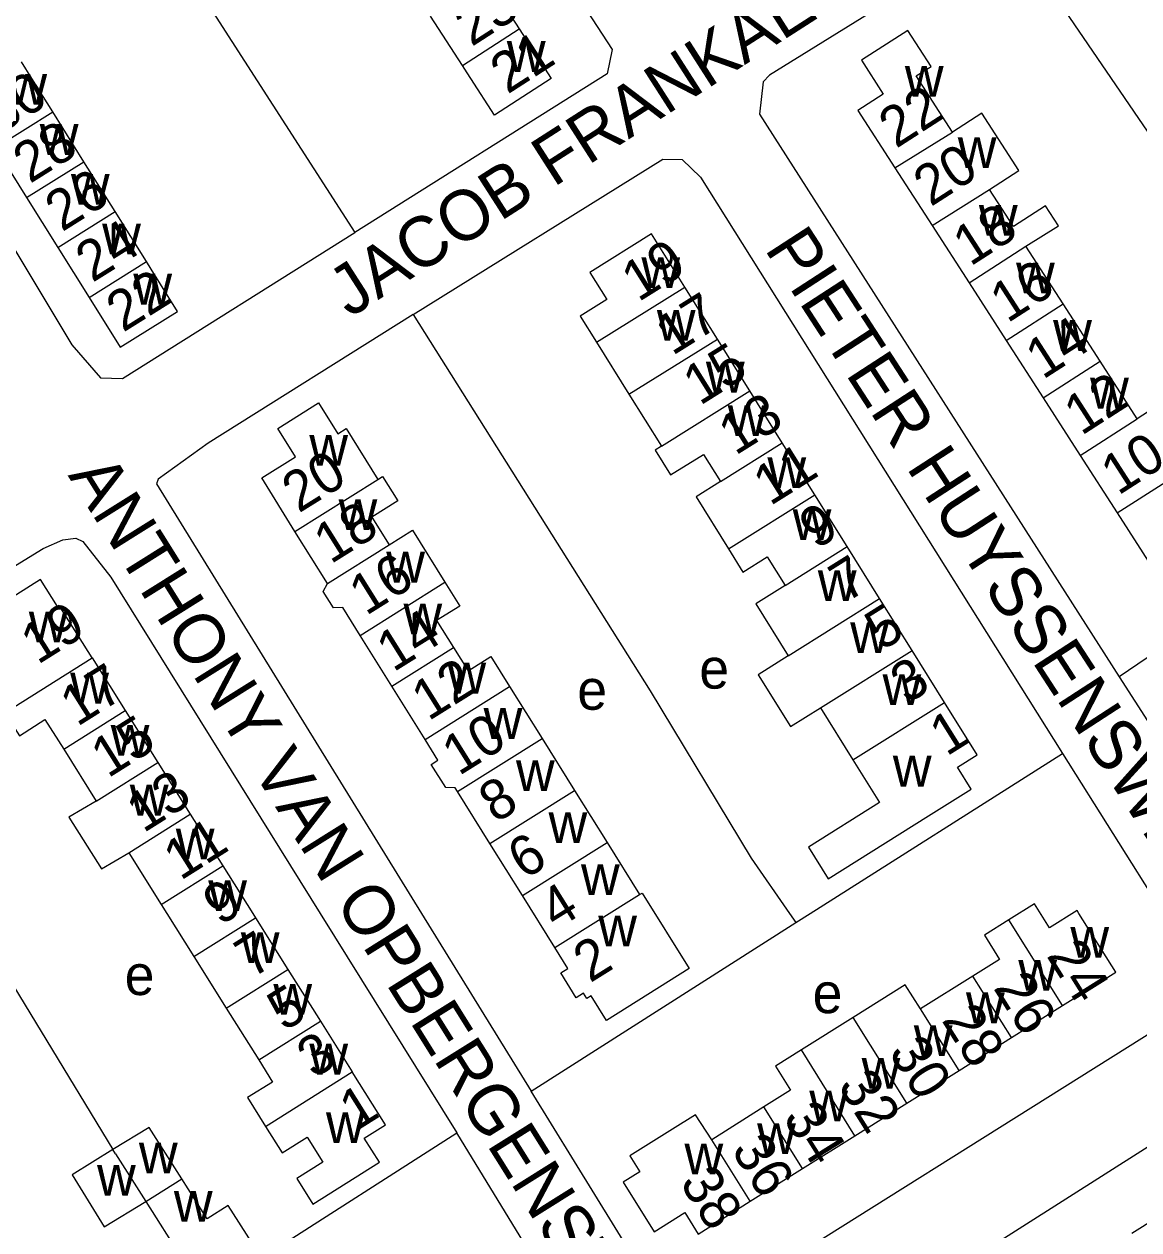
# Model space of a CAD drawing. Extents: x 158848 to 160613, y 385889 to 387762.
# Drawn here: x 159730.4 to 159841.7, y 386135.1 to 386255.4 of the extents above; entities that cross this region are included whole.
import ezdxf

# ---------------------------------------------------------------- set-up
doc = ezdxf.new("R2010")
doc.units = 0
for name, color, linetype in [('BLT_Basislijn', 7, 'Continuous'), ('BLT_Bebouwing', 7, 'Continuous'), ('BLT_Centroide', 7, 'Continuous'), ('BLT_Huisnummer', 7, 'Continuous'), ('BLT_Huisnummer_ tussenligend', 7, 'Continuous'), ('BLT_Onderverdeling_panden', 7, 'Continuous'), ('BLT_Straatnaam', 7, 'Continuous')]:
    doc.layers.add(name, color=color, linetype=linetype)

msp = doc.modelspace()

# ---------------------------------------------------------------- linework, layer by layer
at = {"layer": 'BLT_Basislijn'}
for p, q in [((159733.43, 386281.22), (159763.44, 386234.64)), ((159828.64, 386265.11), (159864.18, 386212.97)), ((159846.93, 386195.16), (159839.72, 386190.3)), ((159839.72, 386190.3), (159844.12, 386183.47)), ((159781.05, 386148.93), (159807.44, 386165.77)), ((159748.59, 386128.77), (159773.6, 386144.78))]:
    msp.add_line(p, q, dxfattribs=at)
for points in [[(159759.78, 386297.89), (159789.12, 386252.89), (159788.61, 386250.47), (159763.44, 386234.64)], [(159709.57, 386266.05), (159735.18, 386223.43), (159738.06, 386220.13), (159740.25, 386220.05), (159763.44, 386234.64)], [(159828.64, 386265.11), (159804.84, 386250.34), (159804.2, 386249.65), (159803.82, 386246.43), (159839.72, 386190.3)], [(159769.26, 386226.44), (159794.19, 386241.94), (159796.12, 386241.93), (159797.93, 386240.15), (159834.08, 386182.64)], [(159769.26, 386226.44), (159748.8, 386213.59), (159743.8, 386210.02), (159743.64, 386209.54), (159770.1, 386166.67), (159781.05, 386148.93)], [(159769.26, 386226.44), (159792.93, 386188.89), (159803.01, 386172.2), (159806.82, 386166.67), (159807.44, 386165.77)], [(159710.52, 386189.71), (159732.33, 386203.09), (159734.29, 386203.97), (159735.57, 386204.11), (159736.27, 386203.79), (159739.07, 386200.22), (159759.97, 386166.67), (159773.6, 386144.78)], [(159710.52, 386189.71), (159724.92, 386166.67), (159739.27, 386143.1)], [(159834.08, 386182.64), (159844.13, 386166.67), (159848.84, 386159.17), (159848.48, 386158.57), (159843.69, 386155.27), (159797.68, 386126.37), (159795.72, 386126.21), (159793.75, 386128.31), (159781.05, 386148.93)], [(159807.44, 386165.77), (159808.87, 386166.67), (159834.08, 386182.64)], [(159748.37, 386051.77), (159734.43, 386074.27), (159734.43, 386074.65), (159846.2, 386145.66), (159847.14, 386145.64), (159848.36, 386145.17), (159861.9, 386123.55)], [(159722.33, 386112.11), (159736.69, 386089.11), (159737.39, 386088.62), (159785.14, 386119), (159786.99, 386121.06), (159786.89, 386123.07), (159773.6, 386144.78)]]:
    msp.add_lwpolyline(points, dxfattribs=at)
at = {"layer": 'BLT_Bebouwing'}
for p, q in [((159776.67, 386259.88), (159779.85, 386254.94)), ((159774.18, 386251.28), (159771, 386256.22)), ((159736.39, 386241.69), (159733.27, 386246.67)), ((159727.56, 386243.09), (159730.67, 386238.11)), ((159739.51, 386236.71), (159736.39, 386241.69)), ((159817.35, 386241.08), (159821.05, 386235.34)), ((159730.67, 386238.11), (159733.79, 386233.13)), ((159742.62, 386231.73), (159739.51, 386236.71)), ((159821.05, 386235.34), (159824.75, 386229.6)), ((159834.13, 386227.52), (159830.43, 386233.26)), ((159733.79, 386233.13), (159736.91, 386228.15)), ((159799.62, 386224), (159796.38, 386229.19)), ((159824.75, 386229.6), (159828.45, 386223.86)), ((159837.83, 386221.78), (159834.13, 386227.52)), ((159802.86, 386218.82), (159799.62, 386224)), ((159828.45, 386223.86), (159832.14, 386218.12)), ((159841.52, 386216.04), (159837.83, 386221.78)), ((159806.1, 386213.64), (159802.86, 386218.82)), ((159832.14, 386218.12), (159835.84, 386212.38)), ((159809.34, 386208.46), (159806.1, 386213.64)), ((159835.84, 386212.38), (159839.54, 386206.64)), ((159812.58, 386203.28), (159809.34, 386208.46)), ((159839.54, 386206.64), (159843.24, 386200.9)), ((159760.71, 386199.61), (159757.46, 386204.8)), ((159815.82, 386198.09), (159812.58, 386203.28)), ((159819.06, 386192.91), (159815.82, 386198.09)), ((159767.12, 386189.35), (159763.95, 386194.42)), ((159822.3, 386187.73), (159819.06, 386192.91)), ((159737.22, 386192.18), (159740.52, 386186.92)), ((159770.44, 386184.04), (159767.12, 386189.35)), ((159778.88, 386189.32), (159782.13, 386184.13)), ((159740.52, 386186.92), (159743.77, 386181.75)), ((159809.93, 386187.2), (159813.16, 386182.01)), ((159782.13, 386184.13), (159785.37, 386178.93)), ((159734.37, 386183.05), (159737.61, 386177.88)), ((159743.77, 386181.75), (159747.01, 386176.58)), ((159776.92, 386173.65), (159773.68, 386178.85)), ((159785.37, 386178.93), (159788.61, 386173.74)), ((159747.01, 386176.58), (159750.26, 386171.41)), ((159780.17, 386168.46), (159776.92, 386173.65)), ((159788.61, 386173.74), (159791.85, 386168.55)), ((159740.86, 386172.71), (159744.1, 386167.55)), ((159753.51, 386166.25), (159756.75, 386161.08)), ((159747.35, 386162.38), (159750.6, 386157.21)), ((159756.75, 386161.08), (159760, 386155.91)), ((159825.12, 386160.42), (159819.91, 386157.15)), ((159828.97, 386154.28), (159834.09, 386157.48)), ((159750.6, 386157.21), (159753.84, 386152.05)), ((159813.19, 386156.29), (159808.01, 386153.05)), ((159760, 386155.91), (159763.17, 386150.87)), ((159823.76, 386151.01), (159828.97, 386154.28)), ((159818.55, 386147.74), (159823.76, 386151.01)), ((159804.27, 386147.36), (159799.06, 386144.09)), ((159813.33, 386144.48), (159818.55, 386147.74)), ((159808.12, 386141.22), (159813.33, 386144.48)), ((159739.53, 386142.67), (159739.27, 386143.1)), ((159802.91, 386137.95), (159808.12, 386141.22)), ((159742.57, 386137.91), (159747.48, 386130.21))]:
    msp.add_line(p, q, dxfattribs=at)
for points in [[(159779.85, 386254.94), (159783.03, 386250), (159777.36, 386246.35), (159775, 386250), (159774.65, 386250.55), (159774.18, 386251.28)], [(159823.1, 386244.64), (159819.48, 386250.25), (159820.95, 386251.19), (159818.62, 386254.8), (159814, 386251.82), (159816.18, 386248.44), (159813.65, 386246.82)], [(159733.27, 386246.67), (159731.19, 386250), (159730.16, 386251.65)], [(159813.65, 386246.82), (159817.35, 386241.08)], [(159826.78, 386238.93), (159829.71, 386240.82), (159826.02, 386246.55), (159823.1, 386244.64)], [(159830.43, 386233.26), (159833.67, 386235.29), (159832.38, 386237.29), (159829.17, 386235.22), (159826.78, 386238.93)], [(159796.38, 386229.19), (159793.06, 386234.49), (159786.89, 386230.64), (159788.59, 386227.93), (159785.92, 386226.27), (159787.55, 386223.67)], [(159736.91, 386228.15), (159740.02, 386223.17), (159745.74, 386226.74), (159743.09, 386230.98), (159742.62, 386231.73)], [(159787.55, 386223.67), (159790.8, 386218.48)], [(159757.46, 386204.8), (159754.14, 386210.13), (159757.51, 386212.23), (159755.73, 386215.07), (159759.81, 386217.62), (159761.74, 386214.54), (159762.57, 386215.06), (159765.74, 386209.98)], [(159790.8, 386218.48), (159794.05, 386213.31)], [(159845.22, 386210.3), (159848.16, 386212.19), (159844.47, 386217.93), (159841.52, 386216.04)], [(159794.05, 386213.31), (159793.41, 386212.9), (159794.95, 386210.43), (159798.23, 386212.48), (159799.92, 386209.78)], [(159765.74, 386209.98), (159766.21, 386210.28), (159767.73, 386207.85), (159765.14, 386206.23), (159766.87, 386203.47)], [(159799.92, 386209.78), (159797.49, 386208.26), (159800.73, 386203.06)], [(159766.87, 386203.47), (159769.19, 386204.92), (159772.43, 386199.73)], [(159800.73, 386203.06), (159802.18, 386200.73), (159804.61, 386202.25), (159806.39, 386199.4)], [(159737.22, 386192.18), (159733.92, 386197.42), (159733.75, 386197.32), (159732.07, 386199.99), (159724.56, 386195.27), (159726.35, 386192.43), (159725.32, 386191.78), (159728.51, 386186.7)], [(159763.95, 386194.42), (159762.22, 386197.2), (159761.31, 386197.16), (159760.27, 386198.81), (159760.71, 386199.61)], [(159772.43, 386199.73), (159773.91, 386197.35), (159771.59, 386195.9), (159773.28, 386193.2)], [(159806.39, 386199.4), (159803.46, 386197.56), (159806.69, 386192.39)], [(159773.28, 386193.2), (159774.73, 386190.88), (159777.02, 386192.31), (159778.88, 386189.32)], [(159806.69, 386192.39), (159803.68, 386190.5), (159806.92, 386185.32), (159809.93, 386187.2)], [(159813.16, 386182.01), (159815.82, 386177.74), (159808.71, 386173.29), (159810.68, 386170.14), (159820.71, 386176.41), (159824.95, 386179.06), (159823.58, 386181.26), (159825.57, 386182.5), (159822.3, 386187.73)], [(159728.51, 386186.7), (159729.95, 386184.41), (159732.5, 386186.02), (159734.37, 386183.05)], [(159773.68, 386178.85), (159773.45, 386179.21), (159772.51, 386179.23), (159771.06, 386181.55), (159771.73, 386181.97), (159770.44, 386184.04)], [(159737.61, 386177.88), (159734.89, 386176.29), (159738.13, 386171.13), (159740.86, 386172.71)], [(159750.26, 386171.41), (159753.24, 386166.67), (159753.51, 386166.25)], [(159783.41, 386163.27), (159780.17, 386168.46)], [(159791.85, 386168.55), (159792.11, 386168.71), (159796.82, 386161.17), (159788.54, 386155.99), (159787.01, 386158.45), (159786.59, 386158.18), (159786.26, 386158.7), (159785.54, 386158.25), (159783.98, 386160.74), (159784.71, 386161.19), (159783.41, 386163.27)], [(159744.1, 386167.55), (159744.66, 386166.67), (159747.35, 386162.38)], [(159834.09, 386157.48), (159839.39, 386160.8), (159835.72, 386166.67), (159835.55, 386166.95), (159832.78, 386165.22), (159831.28, 386167.63), (159828.73, 386166.03)], [(159828.73, 386166.03), (159826.28, 386164.5), (159827.79, 386162.09), (159825.12, 386160.42)], [(159819.91, 386157.15), (159818.37, 386159.54), (159813.19, 386156.29)], [(159808.01, 386153.05), (159805.43, 386151.43), (159806.93, 386149.03), (159804.27, 386147.36)], [(159753.84, 386152.05), (159755.22, 386149.85), (159752.71, 386148.29), (159754.51, 386145.42)], [(159754.51, 386145.42), (159756.17, 386142.79), (159758.67, 386144.36), (159760.24, 386141.86), (159757.65, 386140.22), (159759.25, 386137.67), (159765.89, 386141.84), (159764.38, 386144.25), (159766.49, 386145.58), (159763.17, 386150.87)], [(159799.06, 386144.09), (159797.45, 386146.58), (159795.13, 386145.13), (159790.9, 386142.48), (159791.88, 386140.9), (159790.22, 386139.86), (159793.32, 386134.91), (159796.36, 386136.82), (159797.7, 386134.68), (159802.91, 386137.95)], [(159746.17, 386140.17), (159742.9, 386145.31), (159739.27, 386143.1)], [(159739.27, 386143.1), (159735.2, 386140.6), (159738.42, 386135.39), (159742.57, 386137.91)], [(159747.48, 386130.21), (159753.15, 386133.83), (159750.8, 386137.51), (159748.7, 386136.2), (159746.17, 386140.17)], [(159844.83, 386128.58), (159850.1, 386131.89), (159846.26, 386138.03), (159840.98, 386134.72)]]:
    msp.add_lwpolyline(points, dxfattribs=at)
at = {"layer": 'BLT_Onderverdeling_panden'}
for p, q in [((159774.18, 386251.28), (159779.85, 386254.94)), ((159727.56, 386243.09), (159733.27, 386246.67)), ((159817.35, 386241.08), (159823.1, 386244.64)), ((159730.67, 386238.11), (159736.39, 386241.69)), ((159821.05, 386235.34), (159826.78, 386238.93)), ((159733.79, 386233.13), (159739.51, 386236.71)), ((159824.75, 386229.6), (159830.43, 386233.26)), ((159736.91, 386228.15), (159742.62, 386231.73)), ((159787.55, 386223.67), (159796.38, 386229.19)), ((159828.45, 386223.86), (159834.13, 386227.52)), ((159790.8, 386218.48), (159799.62, 386224)), ((159832.14, 386218.12), (159837.83, 386221.78)), ((159794.05, 386213.31), (159802.86, 386218.82)), ((159835.84, 386212.38), (159841.52, 386216.04)), ((159799.92, 386209.78), (159806.1, 386213.64)), ((159757.46, 386204.8), (159765.74, 386209.98)), ((159839.54, 386206.64), (159845.22, 386210.3)), ((159800.73, 386203.06), (159809.34, 386208.46)), ((159760.71, 386199.61), (159766.87, 386203.47)), ((159806.39, 386199.4), (159812.58, 386203.28)), ((159763.95, 386194.42), (159772.43, 386199.73)), ((159806.69, 386192.39), (159815.82, 386198.09)), ((159767.12, 386189.35), (159773.28, 386193.2)), ((159809.93, 386187.2), (159819.06, 386192.91)), ((159728.51, 386186.7), (159737.22, 386192.18)), ((159770.44, 386184.04), (159778.88, 386189.32)), ((159813.16, 386182.01), (159822.3, 386187.73)), ((159734.37, 386183.05), (159740.52, 386186.92)), ((159773.68, 386178.85), (159782.13, 386184.13)), ((159737.61, 386177.88), (159743.77, 386181.75)), ((159776.92, 386173.65), (159785.37, 386178.93)), ((159740.86, 386172.71), (159747.01, 386176.58)), ((159780.17, 386168.46), (159788.61, 386173.74)), ((159744.1, 386167.55), (159750.26, 386171.41)), ((159783.41, 386163.27), (159791.85, 386168.55)), ((159747.35, 386162.38), (159753.51, 386166.25)), ((159834.09, 386157.48), (159828.73, 386166.03)), ((159750.6, 386157.21), (159756.75, 386161.08)), ((159828.97, 386154.28), (159825.12, 386160.42)), ((159818.55, 386147.74), (159813.19, 386156.29)), ((159823.76, 386151.01), (159819.91, 386157.15)), ((159753.84, 386152.05), (159760, 386155.91)), ((159813.33, 386144.48), (159808.01, 386153.05)), ((159754.51, 386145.42), (159763.17, 386150.87)), ((159808.12, 386141.22), (159804.27, 386147.36)), ((159802.91, 386137.95), (159799.06, 386144.09)), ((159739.53, 386142.67), (159742.57, 386137.91)), ((159742.57, 386137.91), (159746.17, 386140.17))]:
    msp.add_line(p, q, dxfattribs=at)

# ---------------------------------------------------------------- texts
at = {"layer": 'BLT_Centroide'}
for s, p in [('w', (159778.61, 386250.66)), ('w', (159728.85, 386247.38)), ('w', (159818.34, 386248.17)), ('w', (159731.98, 386242.38)), ('w', (159823.62, 386241.06)), ('w', (159735.09, 386237.41)), ('w', (159825.73, 386234.3)), ('w', (159738.21, 386232.44)), ('w', (159792.04, 386229.09)), ('w', (159829.44, 386228.56)), ('w', (159741.32, 386227.44)), ('w', (159793.58, 386223.84)), ('w', (159833.14, 386222.81)), ('w', (159798.48, 386218.66)), ('w', (159836.83, 386217.06)), ('w', (159800.66, 386214.31)), ('w', (159758.89, 386211.36)), ('w', (159804.62, 386209.12)), ('w', (159761.81, 386204.94)), ('w', (159807.14, 386203.94)), ('w', (159766.57, 386199.69)), ('w', (159809.65, 386197.84)), ('w', (159768.29, 386194.53)), ('w', (159730.89, 386193.72)), ('w', (159812.88, 386192.66)), ('w', (159772.67, 386188.62)), ('e', (159797.82, 386189.11)), ('w', (159735.02, 386187.62)), ('e', (159785.64, 386187)), ('w', (159816.11, 386187.47)), ('w', (159776.29, 386184.09)), ('w', (159739.06, 386182.41)), ('w', (159779.52, 386178.88)), ('w', (159817.14, 386179.34)), ('w', (159740.97, 386176.44)), ('w', (159782.77, 386173.69)), ('w', (159745.56, 386172.06)), ('w', (159786.01, 386168.5)), ('w', (159748.8, 386166.91)), ('w', (159787.73, 386163.38)), ('w', (159752.05, 386161.72)), ('w', (159834.86, 386162.25)), ('e', (159740.46, 386158.53)), ('w', (159829.66, 386158.97)), ('e', (159809.13, 386156.72)), ('w', (159755.3, 386156.56)), ('w', (159824.44, 386155.72)), ('w', (159819.23, 386152.45)), ('w', (159758.89, 386150.59)), ('w', (159814.02, 386149.19)), ('w', (159808.8, 386145.92)), ('w', (159760.55, 386143.75)), ('w', (159803.59, 386142.66)), ('w', (159741.88, 386140.72)), ('w', (159796.34, 386140.62)), ('w', (159737.7, 386138.51)), ('w', (159745.37, 386135.9))]:
    msp.add_text(s, height=4, dxfattribs=at).set_placement(p)
at = {"layer": 'BLT_Huisnummer'}
for s, rotation, p in [('21', 32.7765, (159778.67, 386248.38)), ('30', 32.0423, (159728.01, 386244.41)), ('22', 32.7851, (159817.46, 386242.96)), ('26', 32.0423, (159734.19, 386234.64)), ('18', 32.7851, (159824.86, 386231.19)), ('19', 32.0212, (159791.73, 386227.64)), ('22', 32.0423, (159740.29, 386224.61)), ('14', 32.7851, (159832.11, 386219.9)), ('13', 32.0212, (159801.41, 386212.32)), ('10', 32.7851, (159839.63, 386208.33)), ('20', 31.9896, (159757.83, 386206.57)), ('9', 32.0212, (159809.48, 386202.94)), ('19', 32.1357, (159731.77, 386191.45)), ('5', 32.0212, (159816.02, 386192.82)), ('14', 31.9896, (159767.27, 386190.7)), ('10', 31.9896, (159773.81, 386180.35)), ('1', 32.0212, (159822.49, 386182.3)), ('13', 32.1451, (159742.32, 386174.65)), ('6', 31.9896, (159780.36, 386169.99)), ('9', 32.1451, (159749.97, 386165.39)), ('2', 31.9896, (159786.91, 386159.69)), ('24', 302.0657, (159832.42, 386162.47)), ('5', 32.1451, (159756.38, 386154.84)), ('28', 302.0657, (159821.95, 386156.03)), ('32', 302.0657, (159811.56, 386149.48)), ('1', 32.1451, (159763.58, 386144.91)), ('38', 302.0657, (159795.8, 386139.81))]:
    msp.add_text(s, height=4, rotation=rotation, dxfattribs=at).set_placement(p)
at = {"layer": 'BLT_Huisnummer_ tussenligend'}
for s, rotation, p in [('23', 32.7765, (159775.08, 386253.12)), ('28', 32.0423, (159730.99, 386239.46)), ('20', 32.7851, (159820.92, 386237.15)), ('24', 32.0423, (159737.23, 386229.58)), ('16', 32.7851, (159828.57, 386225.53)), ('17', 32.0212, (159795.12, 386222.28)), ('15', 32.0212, (159797.87, 386217.3)), ('12', 32.7851, (159835.95, 386214.3)), ('11', 32.0212, (159804.88, 386207.29)), ('18', 31.9896, (159761.01, 386201.48)), ('16', 31.9896, (159764.54, 386196.33)), ('7', 32.0212, (159812.47, 386197.64)), ('17', 32.1451, (159735.71, 386185.26)), ('12', 31.9896, (159770.77, 386185.82)), ('3', 32.0212, (159818.57, 386187.53)), ('15', 32.1451, (159738.78, 386180.12)), ('8', 31.9896, (159777.48, 386175.62)), ('11', 32.1451, (159746.02, 386169.9)), ('4', 31.9896, (159783.52, 386164.99)), ('7', 32.1451, (159753.15, 386160.14)), ('26', 302.0657, (159827.11, 386159.25)), ('3', 32.1451, (159759.34, 386150.14)), ('30', 302.0657, (159816.64, 386152.82)), ('34', 302.0657, (159806.09, 386146.28)), ('36', 302.0657, (159800.94, 386143.06))]:
    msp.add_text(s, height=4, rotation=rotation, dxfattribs=at).set_placement(p)
at = {"layer": 'BLT_Straatnaam'}
for s, rotation, p in [('JACOB FRANKAERTWEG', 32.6604, (159762.92, 386226.06)), ('PIETER HUYSSENSWEG', 302.9892, (159804.26, 386233)), ('ANTHONY VAN OPBERGENSTRAAT', 302.0451, (159734.75, 386210.39))]:
    msp.add_text(s, height=5, rotation=rotation, dxfattribs=at).set_placement(p)

doc.saveas('drawing.dxf')
